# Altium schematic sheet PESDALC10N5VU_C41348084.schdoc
size 127 x 101 mm
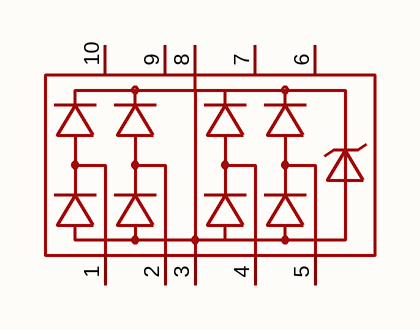
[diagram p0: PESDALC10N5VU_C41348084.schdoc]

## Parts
D?  pesdalc10n5vu_c41348084  [DFN2510-10_L2.5-W1.0-P0.50-BL]  (value not drawn)

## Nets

Not connected (* = marked no-connect by the designer): D? 1 2 3 4 5 6 7 8 9 10

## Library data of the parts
D? = pesdalc10n5vu_c41348084: 极性:单向;反向截止电压(Vrwm):5V;钳位电压:16V;峰值脉冲电流(Ipp):4A@8/20us;峰值脉冲功率(Ppp):80W@8/20us;击穿电压:9.5V;; Manufacturer: TECH PUBLIC(台舟); AddInBom: yes; ModelId: 55525fa8fc914f7c8ffcb10749ea5f73; ModelName: DFN-10_L2.5-W1.0-H0.5-P0.50; ModelTransform: 40.1574,98.425,0,90,0,0,0,0,0; Polarity: 单向; Reverse Stand-Off Voltage (Vrwm): 5V; Clamping Voltage: 16V; Voltage - Breakdown: 9.5V; Reverse Leakage Current (Ir): 100nA; Number of Channels: 四路; level of protection: IEC 61000-4-4；IEC 61000-4-5；IEC 61000-4-2; Type: TVS; Junction Capacitance: 0.8pF；0.3pF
